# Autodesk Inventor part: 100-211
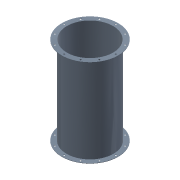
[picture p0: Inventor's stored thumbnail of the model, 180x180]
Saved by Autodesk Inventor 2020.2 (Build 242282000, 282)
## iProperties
Created: 2011-01
Part Number: 100-211
Document SubType Name: Modeling
Designer: F.Stasiak
Density: 1 g/cm^3
Material: Ogólny
Appearance: Stalowoniebieska
Company: Fabian Stasiak CAD Consulting
Manager: www.cadconsulting.pl
Author: F.Stasiak
Subject: Zbiór ćwiczeń. Autodesk Inventor 2020. Kurs podstawowy
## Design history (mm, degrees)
sketch "Szkic1"
  geometry: C1 r 200 at (0, 0); C2 r 197 at (0, 0); 1 further point
  constraints: 2 centre point, 2 coincident
  dimensions: "d0" = 400 diameter of C1; "d1" = 3 radial gap between concentric circles of C1 C2
extrude "Wyciągnięcie proste1" new body sketch "Szkic1" distance "d2" = 750; taper "d3" = 0 deg
sketch "Szkic2"
  geometry: C1 r 200 at (0, 0) reference; C2 r 240 at (0, 0); 1 further point
  constraints: 1 centre point
  dimensions: "d4" = 40 radial gap between concentric circles of C2 C1
extrude "Wyciągnięcie proste2" join sketch "Szkic2" distance "d5" = 3; taper "d6" = 0 deg
sketch "Szkic3"
  geometry: C1 r 200 at (0, 0) reference; C2 r 240 at (0, 0); 1 further point
  constraints: 1 centre point
  dimensions: "d7" = 40 radial gap between concentric circles of C2 C1
extrude "Wyciągnięcie proste3" join sketch "Szkic3" distance "d8" = 3; taper "d9" = 0 deg
sketch "Szkic4"
  geometry: 2 further points
  dimensions: "d10" = 220 distance of point (0, 220) point (0, 0)
hole "Hole1" sketch "Szkic4" at (0, 220) diameter "d11" = 13; stored, may be unused: countersink angle "d15" = 90 deg, drill point angle "d17" = 118 deg; dims "d12" = 6, "d13" = 4, "d14" = 2, "d16" = 8
pattern_circular "Szyk kołowy1" dims angle "d19" = 360 deg
sketch "Szkic5"
  geometry: L1 (-125, 350)-(125, 350); L2 (125, 350)-(125, 100); L3 (125, 100)-(-125, 100); L4 (-125, 100)-(-125, 350); L5 (0, -150)-(0, 900) reference; L6 (197, 0)-(-197, 0) reference; 2 further points
  constraints: 8 end point, 2 parallel, 1 horizontal, 1 midpoint, 1 perpendicular, 1 point on line
  dimensions: "d21" = 250 distance of L2.end L3.end; "d22" = 250 distance of L1.end L2.end; "d23" = 100 distance between parallel lines of L6 L3
extrude "Wyciągnięcie proste4" cut sketch "Szkic5" extent not by distance; stored distance "d24" = 3; taper "d25" = 0 deg
node "Bryła1"
